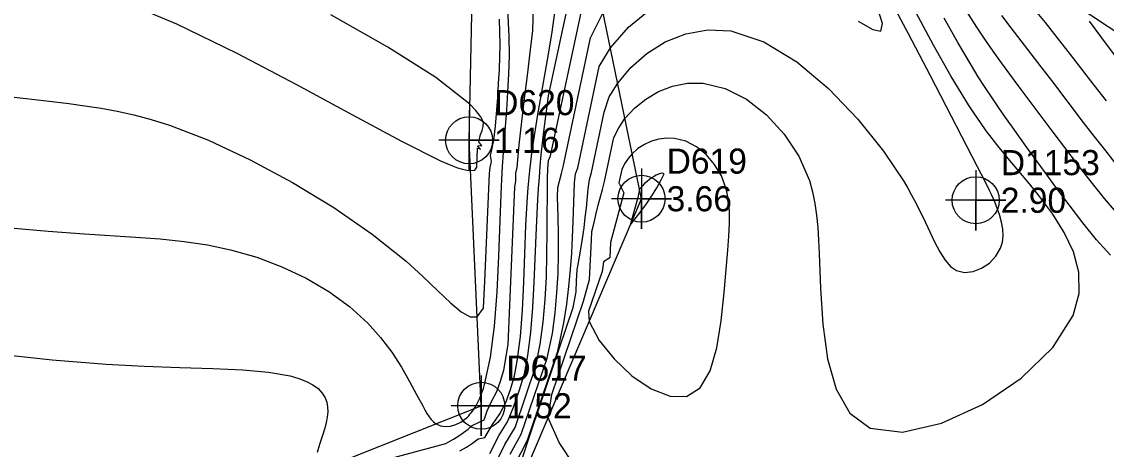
# Model space of a CAD drawing. Extents: x 2356077 to 2359823, y 225951 to 227822.
# Drawn here: x 2357348.2 to 2357456.1, y 226718.9 to 226761.5 of the extents above; entities that cross this region are included whole.
import ezdxf

# ---------------------------------------------------------------- set-up
doc = ezdxf.new("R2010")
doc.units = 0
for name, color, linetype in [('DTM Contours Major', 7, 'Continuous'), ('DTM Contours Minor', 7, 'Continuous'), ('Exist DTM Breakline', 7, 'Continuous'), ('Exist DTM Breakline Cogo Elevation', 7, 'Continuous'), ('Exist DTM Breakline Cogo Number', 7, 'Continuous'), ('Exist DTM Breakline Cogo Point CELL', 7, 'Continuous'), ('Exist DTM Regular Point CELL', 7, 'Continuous'), ('Exist DTM Regular Point Cogo Elevation', 7, 'Continuous'), ('Exist DTM Regular Point Cogo Number', 7, 'Continuous'), ('PH Exist DTM Breakline', 7, 'Continuous'), ('PH Exist DTM Point', 7, 'Continuous')]:
    doc.layers.add(name, color=color, linetype=linetype)

msp = doc.modelspace()

# ---------------------------------------------------------------- linework, layer by layer
at = {"layer": 'DTM Contours Major'}
for points in [[(2357397.82, 226717.46), (2357398.92, 226720.88), (2357403.04, 226733.05), (2357403.34, 226734.59), (2357403.39, 226735.68), (2357403.45, 226736.79), (2357403.72, 226738.26), (2357403.94, 226739.66), (2357404.13, 226740.98), (2357404.25, 226741.99), (2357404.36, 226742.96), (2357404.55, 226744.86), (2357404.66, 226745.77), (2357404.87, 226746.46), (2357406.15, 226752.47), (2357406.63, 226754), (2357407.48, 226755.38), (2357408.78, 226756.93), (2357410.38, 226758.32), (2357412.22, 226759.47), (2357414.26, 226760.28), (2357416.44, 226760.67), (2357418.73, 226760.57), (2357422.03, 226759.48), (2357425.32, 226757.49), (2357428.47, 226754.85), (2357431.38, 226751.8), (2357433.92, 226748.61), (2357435.98, 226745.53), (2357436.35, 226744.9), (2357436.69, 226744.29), (2357437.02, 226743.69), (2357437.32, 226743.11), (2357437.6, 226742.55), (2357437.87, 226742.01), (2357439.02, 226739.58), (2357439.54, 226738.58), (2357440.06, 226737.76), (2357440.61, 226737.13), (2357441.21, 226736.72), (2357442.01, 226736.53), (2357442.86, 226736.61), (2357443.7, 226736.94), (2357444.48, 226737.46), (2357445.12, 226738.14), (2357445.59, 226738.94), (2357445.77, 226739.53), (2357445.84, 226740.17), (2357445.81, 226740.83), (2357445.68, 226741.54), (2357445.48, 226742.29), (2357445.19, 226743.08), (2357445.04, 226743.47), (2357444.87, 226743.86), (2357444.68, 226744.27), (2357444.48, 226744.7), (2357444.04, 226745.59), (2357443.3, 226747.05), (2357438.61, 226756.1), (2357436.42, 226760.28), (2357434.2, 226764.47)], [(2357391.78, 226718.75), (2357392.43, 226719.14), (2357393.04, 226719.54), (2357393.6, 226719.96), (2357394.25, 226720.09), (2357395.01, 226721.37), (2357395.75, 226722.43), (2357396.35, 226723.59), (2357396.82, 226724.86), (2357397.2, 226726.22), (2357397.48, 226727.69), (2357397.8, 226730.14), (2357398, 226732.78), (2357398.13, 226735.54), (2357398.23, 226738.38), (2357398.34, 226741.23), (2357398.5, 226744.04), (2357398.56, 226744.94), (2357398.74, 226746.66), (2357398.84, 226747.52), (2357398.94, 226748.39), (2357399.06, 226749.25), (2357399.5, 226752.05), (2357399.99, 226754.88), (2357400.48, 226757.69), (2357400.95, 226760.45), (2357401.33, 226763.13)], [(2357456.14, 226753.6), (2357454.91, 226755.18), (2357452.45, 226758.37), (2357451.23, 226759.93), (2357450.05, 226761.4), (2357448.9, 226762.79)]]:
    msp.add_lwpolyline(points, dxfattribs=at)
at = {"layer": 'DTM Contours Minor'}
for points in [[(2357394.74, 226718.49), (2357395.67, 226720.33), (2357396.52, 226721.64), (2357397.11, 226723.1), (2357397.66, 226724.74), (2357398.2, 226726.43), (2357398.53, 226728.26), (2357398.82, 226730.58), (2357399.02, 226733.02), (2357399.16, 226735.57), (2357399.39, 226740.97), (2357399.53, 226743.79), (2357399.61, 226744.88), (2357399.69, 226745.98), (2357399.78, 226747.09), (2357399.88, 226748.23), (2357400, 226749.39), (2357400.12, 226750.57), (2357400.6, 226754.12), (2357402.78, 226764.33)], [(2357357.84, 226763.69), (2357363.56, 226761.28), (2357369.56, 226758.36), (2357375.51, 226755.24), (2357381.09, 226752.22), (2357385.98, 226749.59), (2357389.84, 226747.65), (2357390.46, 226747.37), (2357391.03, 226747.13), (2357391.55, 226746.94), (2357392.03, 226746.8), (2357392.45, 226746.71), (2357392.83, 226746.68), (2357393.25, 226746.72), (2357393.46, 226747), (2357393.54, 226748.91), (2357393.6, 226748.9), (2357393.69, 226748.87), (2357393.84, 226748.8), (2357393.56, 226749.08), (2357393.58, 226749.15), (2357393.95, 226749.12), (2357393.67, 226749.52), (2357393.83, 226750.27), (2357393.98, 226750.66), (2357394.1, 226751.06), (2357394.13, 226751.5), (2357393.83, 226752.05), (2357393.36, 226752.65), (2357392.77, 226753.28), (2357389.39, 226755.95), (2357384.59, 226758.97), (2357378.93, 226762.17)], [(2357395.09, 226717.03), (2357396.25, 226719.4), (2357397.27, 226721.09), (2357399.34, 226727.2), (2357399.77, 226729.38), (2357400.06, 226731.59), (2357400.26, 226733.82), (2357400.38, 226736.06), (2357400.44, 226738.32), (2357400.47, 226740.58), (2357400.48, 226745.87), (2357400.52, 226746.83), (2357400.6, 226747.66), (2357400.8, 226748.13), (2357404.01, 226763.18)], [(2357347.04, 226740.98), (2357350.81, 226740.63), (2357354.43, 226740.36), (2357359.5, 226740.04), (2357361.94, 226739.86), (2357364.32, 226739.62), (2357366.65, 226739.27), (2357368.96, 226738.79), (2357371.55, 226738.05), (2357374.07, 226737.09), (2357376.48, 226735.95), (2357378.73, 226734.62), (2357380.79, 226733.13), (2357382.6, 226731.49), (2357383.88, 226730.05), (2357385, 226728.57), (2357385.95, 226727.09), (2357386.77, 226725.68), (2357387.47, 226724.38), (2357388.08, 226723.24), (2357388.29, 226722.84), (2357388.5, 226722.48), (2357388.71, 226722.16), (2357388.93, 226721.88), (2357389.16, 226721.65), (2357389.41, 226721.46), (2357389.84, 226721.26), (2357390.32, 226721.18), (2357390.84, 226721.22), (2357391.36, 226721.37), (2357391.88, 226721.63), (2357392.39, 226722.01), (2357392.52, 226722.13), (2357392.65, 226722.26), (2357392.77, 226722.4), (2357392.9, 226722.54), (2357393.02, 226722.7), (2357393.13, 226722.86), (2357393.35, 226723.21), (2357393.56, 226723.6), (2357393.76, 226724.02), (2357393.94, 226724.47), (2357394.11, 226724.96), (2357394.27, 226725.49), (2357394.83, 226728.09), (2357395.21, 226731.18), (2357395.47, 226734.58), (2357395.65, 226738.15), (2357395.79, 226741.71), (2357395.93, 226745.11), (2357396.03, 226747.06), (2357396.16, 226748.92), (2357396.44, 226752.67), (2357396.56, 226754.49), (2357396.66, 226756.3), (2357396.71, 226758.14), (2357396.69, 226760.03), (2357396.56, 226762.75)], [(2357381.62, 226717.15), (2357390.38, 226719.49), (2357390.62, 226719.62), (2357391.15, 226719.93), (2357391.66, 226720.25), (2357392.14, 226720.58), (2357392.59, 226720.93), (2357393.01, 226721.28), (2357394.19, 226721.85), (2357394.5, 226722.76), (2357394.97, 226723.73), (2357395.44, 226724.68), (2357395.83, 226725.71), (2357396.16, 226726.81), (2357396.59, 226729.36), (2357397.26, 226745.03), (2357397.33, 226745.66), (2357397.34, 226746.41), (2357397.49, 226746.99), (2357397.55, 226747.74), (2357397.61, 226748.48), (2357397.67, 226749.22), (2357397.93, 226751.54), (2357398.22, 226753.85), (2357398.51, 226756.14), (2357398.77, 226758.41), (2357399.04, 226760.63), (2357399.1, 226762.89)], [(2357396.79, 226718.42), (2357397.89, 226720.43), (2357400.45, 226728), (2357400.98, 226730.46), (2357401.25, 226732.5), (2357401.44, 226734.5), (2357401.55, 226736.46), (2357401.6, 226738.38), (2357401.6, 226740.26), (2357401.56, 226742.1), (2357401.49, 226744.03), (2357401.51, 226744.97), (2357401.9, 226746.39), (2357402.04, 226747.04), (2357404.78, 226759.88), (2357406.03, 226762.41)], [(2357397.23, 226717.38), (2357398.52, 226719.81), (2357401.52, 226728.67), (2357402.12, 226731.52), (2357402.41, 226733.36), (2357402.63, 226735.12), (2357402.79, 226736.82), (2357402.9, 226738.46), (2357402.98, 226740.05), (2357403.05, 226741.6), (2357403.15, 226744.48), (2357403.19, 226745.44), (2357403.27, 226746.35), (2357403.5, 226746.94), (2357405.65, 226757.03), (2357406.75, 226758.89), (2357408.54, 226760.93), (2357410.73, 226762.74)], [(2357403.21, 226717.24), (2357401.65, 226719.59), (2357400.57, 226722.06), (2357400.94, 226724.37), (2357404.08, 226733.65), (2357404.69, 226735.83), (2357404.86, 226739.73), (2357404.92, 226740.61), (2357405.13, 226741.5), (2357405.33, 226742.38), (2357405.54, 226743.21), (2357405.97, 226744.79), (2357406.16, 226745.59), (2357407.09, 226749.96), (2357407.58, 226750.93), (2357408.2, 226751.86), (2357409.14, 226752.88), (2357410.27, 226753.79), (2357411.55, 226754.53), (2357412.95, 226755.07), (2357414.44, 226755.36), (2357415.98, 226755.37), (2357418.17, 226754.85), (2357420.31, 226753.78), (2357422.3, 226752.23), (2357424.06, 226750.3), (2357425.51, 226748.09), (2357426.56, 226745.67), (2357426.87, 226744.55), (2357427.11, 226743.4), (2357427.27, 226742.22), (2357427.39, 226741), (2357427.47, 226739.73), (2357427.53, 226738.42), (2357427.66, 226734.94), (2357427.9, 226731.36), (2357428.37, 226727.92), (2357429.22, 226724.89), (2357430.58, 226722.5), (2357432.6, 226721.01), (2357435.84, 226720.62), (2357439.72, 226721.51), (2357443.79, 226723.39), (2357447.63, 226725.99), (2357450.78, 226729.04), (2357452.82, 226732.25), (2357453.4, 226734.43), (2357453.36, 226736.54), (2357452.83, 226738.58), (2357451.93, 226740.51), (2357450.78, 226742.34), (2357449.51, 226744.05), (2357448.91, 226744.8), (2357448.31, 226745.54), (2357446.5, 226747.68), (2357445.91, 226748.4), (2357445.33, 226749.12), (2357444.75, 226749.87), (2357444.16, 226750.64), (2357443.58, 226751.45), (2357442.99, 226752.31), (2357442.39, 226753.22), (2357440.67, 226756.03), (2357438.91, 226759.15), (2357437.14, 226762.43)], [(2357431.4, 226761.54), (2357432.86, 226760.7), (2357433.68, 226760.55), (2357433.82, 226761.31), (2357433.33, 226762.86)], [(2357457.14, 226742.48), (2357455.93, 226743.88), (2357454.72, 226745.38), (2357453.53, 226746.92), (2357452.61, 226748.12), (2357450.82, 226750.5), (2357447.34, 226755.13), (2357446.5, 226756.27), (2357445.67, 226757.4), (2357444.84, 226758.56), (2357444.02, 226759.74), (2357443.22, 226760.94), (2357442.16, 226762.62)], [(2357457, 226747.44), (2357455.96, 226748.75), (2357454.91, 226750.1), (2357453.85, 226751.47), (2357450.69, 226755.64), (2357449.64, 226757.01), (2357446.65, 226760.87), (2357445.7, 226762.1)], [(2357343.15, 226754.45), (2357348.3, 226753.88), (2357350.63, 226753.62), (2357352.85, 226753.35), (2357354.45, 226753.13), (2357356.06, 226752.89), (2357357.68, 226752.59), (2357359.34, 226752.22), (2357361.06, 226751.76), (2357362.87, 226751.19), (2357366.76, 226749.68), (2357370.9, 226747.75), (2357375.12, 226745.49), (2357379.23, 226742.99), (2357383.06, 226740.34), (2357386.43, 226737.65), (2357388.1, 226736.12), (2357389.57, 226734.7), (2357390.84, 226733.49), (2357391.91, 226732.59), (2357392.79, 226732.1), (2357393.49, 226732.11), (2357394.14, 226732.96), (2357394.27, 226735.64), (2357394.73, 226746.38), (2357394.8, 226746.98), (2357394.85, 226747.28), (2357394.91, 226747.57), (2357394.82, 226748.18), (2357394.89, 226748.45), (2357395.17, 226749.68), (2357395.32, 226751.1), (2357395.54, 226753.93), (2357395.63, 226755.33), (2357395.71, 226756.75), (2357395.78, 226759.23), (2357395.72, 226761.73)], [(2357456.54, 226738.25), (2357455.15, 226739.78), (2357453.76, 226741.47), (2357452.4, 226743.25), (2357451.08, 226745.02), (2357449.58, 226747.07), (2357448.15, 226749.05), (2357446.76, 226750.99), (2357446.09, 226751.95), (2357445.41, 226752.92), (2357444.74, 226753.92), (2357444.06, 226754.94), (2357443.37, 226756.01), (2357442.68, 226757.13), (2357441.33, 226759.42), (2357439.96, 226761.84)], [(2357458.3, 226756.36), (2357455.68, 226759.89), (2357454.43, 226761.53)], [(2357406.77, 226739.52), (2357406.7, 226737.99), (2357406.06, 226737.57), (2357405.93, 226736.63), (2357404.59, 226732.68), (2357404.65, 226731.64), (2357405.64, 226729.76), (2357407.12, 226727.91), (2357408.9, 226726.24), (2357410.82, 226724.95), (2357412.69, 226724.2), (2357414.33, 226724.16), (2357415.69, 226725.04), (2357416.67, 226726.74), (2357417.34, 226729.03), (2357417.78, 226731.7), (2357418.08, 226734.53), (2357418.45, 226738.75), (2357418.55, 226740.12), (2357418.61, 226741.41), (2357418.61, 226742.63), (2357418.51, 226743.77), (2357418.29, 226744.84), (2357417.81, 226746.13), (2357417.13, 226747.28), (2357416.28, 226748.26), (2357415.31, 226749.03), (2357414.26, 226749.58), (2357413.15, 226749.87), (2357412.36, 226749.9), (2357411.59, 226749.81), (2357410.84, 226749.59), (2357410.14, 226749.27), (2357409.49, 226748.85), (2357408.93, 226748.35), (2357408.52, 226747.87), (2357408.17, 226747.34), (2357407.89, 226746.77), (2357407.6, 226745.45), (2357408.1, 226744.45), (2357406.77, 226739.52)], [(2357409.47, 226743.99), (2357408.73, 226741.22), (2357409.56, 226742.29), (2357410.28, 226743.26), (2357410.89, 226744.14), (2357411.39, 226744.94), (2357411.79, 226745.67), (2357412.11, 226746.35), (2357412.02, 226746.39), (2357411.9, 226746.4), (2357411.74, 226746.37), (2357411.54, 226746.31), (2357411.3, 226746.21), (2357411.04, 226746.06), (2357410.84, 226745.93), (2357410.63, 226745.77), (2357410.4, 226745.59), (2357410.16, 226745.37), (2357409.91, 226745.12), (2357409.65, 226744.83), (2357409.47, 226743.99)], [(2357345.66, 226728.41), (2357351.2, 226727.83), (2357356.57, 226727.39), (2357360.35, 226727.2), (2357363.91, 226727.07), (2357367.2, 226726.96), (2357370.16, 226726.82), (2357372.74, 226726.59), (2357374.88, 226726.22), (2357375.75, 226725.97), (2357376.51, 226725.68), (2357377.15, 226725.34), (2357377.67, 226724.96), (2357378.07, 226724.52), (2357378.36, 226724.03), (2357378.52, 226723.6), (2357378.6, 226723.13), (2357378.62, 226722.63), (2357378.57, 226722.11), (2357378.48, 226721.57), (2357378.34, 226721.02), (2357378.08, 226720.2), (2357377.8, 226719.38), (2357377.58, 226718.61)]]:
    msp.add_lwpolyline(points, dxfattribs=at)
at = {"layer": 'Exist DTM Breakline'}
for points in [[(2357330.12, 226701.28), (2357367.05, 226712.54), (2357393.9, 226723.25), (2357392.69, 226749.68), (2357393.34, 226779.57), (2357395.63, 226793.61)], [(2357367.05, 226712.54), (2357393.9, 226723.25), (2357392.69, 226749.68), (2357393.34, 226779.57), (2357395.63, 226793.61)], [(2357351.86, 226686.88), (2357362.09, 226692.85), (2357395.95, 226711.24), (2357409.85, 226743.86), (2357404.44, 226770.1), (2357423.96, 226775.63)], [(2357362.09, 226692.85), (2357395.95, 226711.24), (2357409.85, 226743.86), (2357404.44, 226770.1), (2357423.96, 226775.63)]]:
    msp.add_lwpolyline(points, dxfattribs=at)
at = {"layer": 'Exist DTM Breakline Cogo Point CELL'}
for points in [[(2357392.69, 226752.68), (2357392.69, 226746.68), (2357392.69, 226749.68), (2357395.69, 226749.68), (2357389.69, 226749.68)], [(2357409.85, 226746.86), (2357409.85, 226740.86), (2357409.85, 226743.86), (2357412.85, 226743.86), (2357406.85, 226743.86)], [(2357393.9, 226726.25), (2357393.9, 226720.25), (2357393.9, 226723.25), (2357396.9, 226723.25), (2357390.9, 226723.25)]]:
    msp.add_lwpolyline(points, dxfattribs=at)
for centre in [(2357392.69, 226749.68), (2357409.85, 226743.86), (2357393.9, 226723.25)]:
    msp.add_circle(centre, 2.34, dxfattribs=at)
at = {"layer": 'Exist DTM Regular Point CELL'}
msp.add_lwpolyline([(2357443.11, 226746.71), (2357443.11, 226740.71), (2357443.11, 226743.71), (2357446.11, 226743.71), (2357440.11, 226743.71)], dxfattribs=at)
msp.add_circle((2357443.11, 226743.71), 2.34, dxfattribs=at)
at = {"layer": 'PH Exist DTM Breakline'}
msp.add_lwpolyline([(2357466.75, 226754.09), (2357452.77, 226763.31), (2357443.12, 226770.29), (2357432.93, 226777.16), (2357423.63, 226781.67), (2357414.78, 226785.2), (2357406.24, 226788.43), (2357395.63, 226793.61), (2357389.13, 226799.36), (2357382.25, 226804.93), (2357375.36, 226810.35), (2357370.57, 226815.95), (2357365.48, 226820.16), (2357357.35, 226824.66), (2357348.41, 226829.41), (2357338.4, 226834.83), (2357329.33, 226839.83), (2357322.09, 226843.76)], dxfattribs=at)
at = {"layer": 'PH Exist DTM Point'}
msp.add_line((2357378.27, 226722.19), (2357378.27, 226722.19), dxfattribs=at)

# ---------------------------------------------------------------- texts
at = {"layer": 'Exist DTM Breakline Cogo Elevation'}
for s, p in [('1.16', (2357395.19, 226748.43)), ('3.66', (2357412.35, 226742.61)), ('1.52', (2357396.4, 226722))]:
    msp.add_text(s, height=2.5, dxfattribs=at).set_placement(p)
at = {"layer": 'Exist DTM Breakline Cogo Number'}
for s, p in [('D620', (2357395.19, 226752.18)), ('D619', (2357412.35, 226746.36)), ('D617', (2357396.4, 226725.75))]:
    msp.add_text(s, height=2.5, dxfattribs=at).set_placement(p)
at = {"layer": 'Exist DTM Regular Point Cogo Elevation'}
msp.add_text('2.90', height=2.5, dxfattribs=at).set_placement((2357445.61, 226742.46))
at = {"layer": 'Exist DTM Regular Point Cogo Number'}
msp.add_text('D1153', height=2.5, dxfattribs=at).set_placement((2357445.61, 226746.21))

doc.saveas('drawing.dxf')
